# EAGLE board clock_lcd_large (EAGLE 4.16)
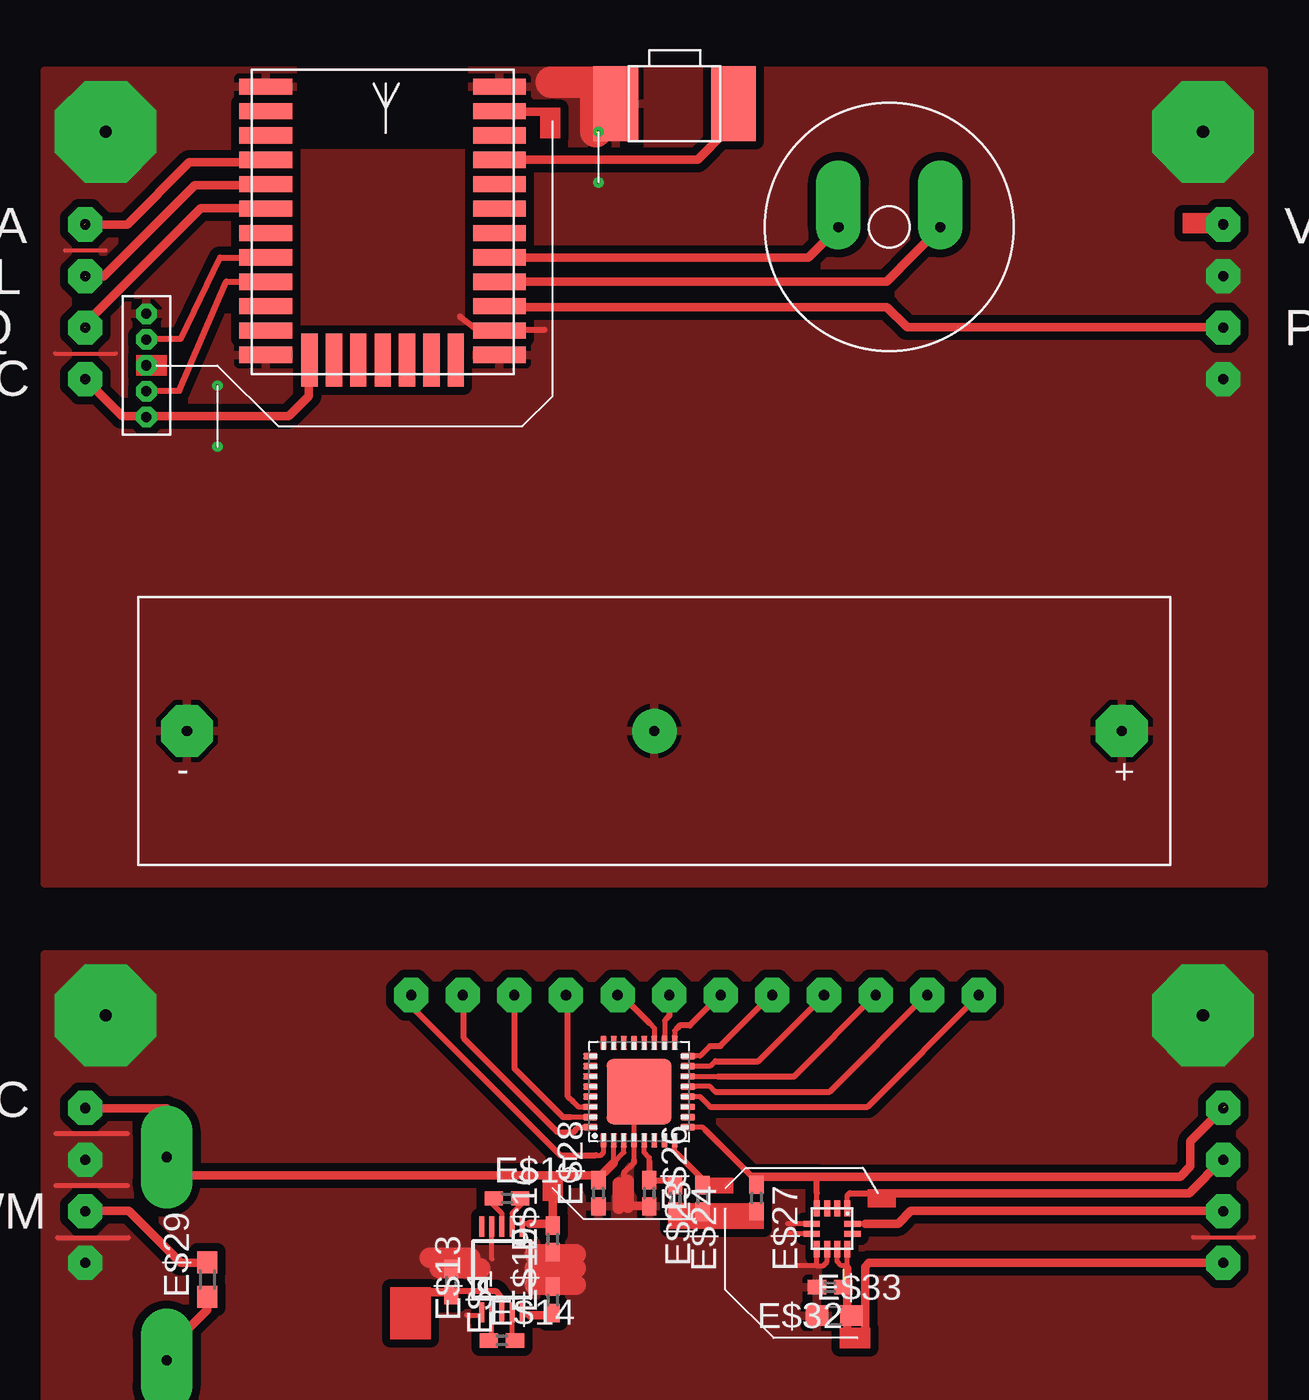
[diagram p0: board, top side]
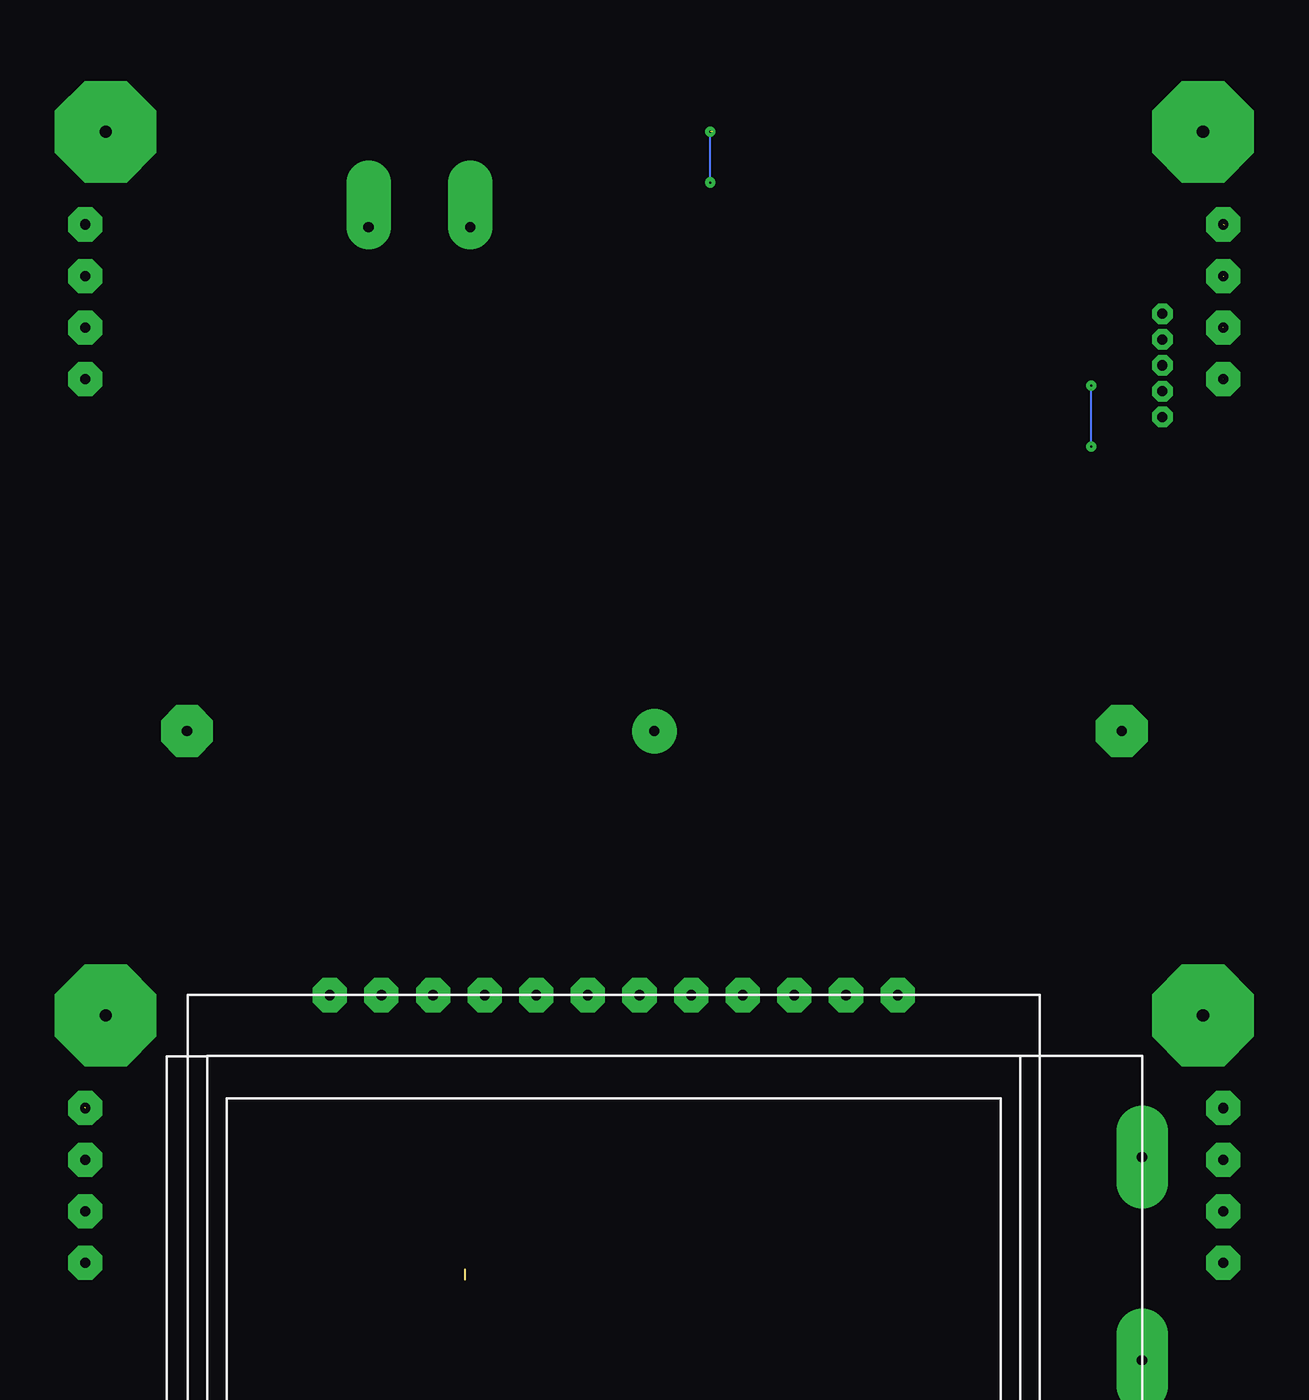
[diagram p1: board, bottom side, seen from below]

Size 0 x 0.5 mm. Coordinates in mm from the lower left corner, seen from the top.
Outline: 0,0 0,0.5
Copper layers (1*16): Top 0.035mm / dielectric 1.5mm / Bottom 0.035mm
Design rules "default": minimum track width 10mil, minimum drill 24mil, track to track 8mil, track to pad 8mil, pad to pad 8mil, via to via 8mil, smd to smd 8mil, copper to edge 40mil, drill to drill 8mil, minimum pad ring 10mil, minimum via ring 8mil, stop-mask expansion 4mil, vias tented up to drill 0mil, thermal gap 10mil

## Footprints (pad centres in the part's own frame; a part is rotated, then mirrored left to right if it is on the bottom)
C0402 = smd 0.9 x 0.7: 1 -0.65,0; 2 0.65,0
HEADER5SH = drill 0.5 octagon: P$1 -2.54,0; P$2 -1.27,0; P$3 0,0; P$4 2.54,0; P$5 1.27,0
BUZZ_12MM = drill 0.5 pad 2.184 offset: P$1 -2.5,0; P$2 2.5,0
ALI_4D_12 = drill 0.5 pad 1.676 octagon: 1 -13.97,0; 2 -11.43,0; 3 -8.89,0; 4 -6.35,0; 5 -3.81,0; 6 -1.27,0; 7 1.27,0; 8 3.81,0; 9 6.35,0; 10 8.89,0; 11 11.43,0; 12 13.97,0 | drill 0.5 pad 2.54 long: A -26,7.97; K -26,17.97
MSOP10 = smd 0.25 x 1: 1 -1,-2.113; 2 -0.5,-2.113; 3 0,-2.113; 4 0.5,-2.113; 5 1,-2.113; 6 1,2.113; 7 0.5,2.113; 8 0,2.113; 9 -0.5,2.113; 10 -1,2.113
AAA_MPD = drill 0.5 pad 2.184 round: P$1 0,0 | drill 0.5 pad 2.54 octagon: P$2 23,0; P$3 -23,0
QFN32 = smd 0.7 x 0.3: 1 -2.15,2; 2 -2.15,1.5; 3 -2.15,1; 4 -2.15,0.5; 5 -2.15,0; 6 -2.15,-0.5; 7 -2.15,-1; 8 -2.15,-1.5; 17 2.65,-1.5; 18 2.65,-1; 19 2.65,-0.5; 20 2.65,0; 21 2.65,0.5; 22 2.65,1; 23 2.65,1.5; 24 2.65,2 | smd 0.3 x 0.7: 9 -1.5,-2.15; 10 -1,-2.15; 11 -0.5,-2.15; 12 0,-2.15; 13 0.5,-2.15; 14 1,-2.15; 15 1.5,-2.15; 16 2,-2.15; 25 2,2.65; 26 1.5,2.65; 27 1,2.65; 28 0.5,2.65; 29 0,2.65; 30 -0.5,2.65; 31 -1,2.65; 32 -1.5,2.65 | smd 3.2 x 3.2: EXP 0.25,0.25
R0603 = smd 1.1 x 1: 1 -0.85,0; 2 0.85,0
LGA12 = smd 0.8 x 0.3: 1 -0.75,0.5; 2 -0.75,0; 3 -0.75,-0.5; 4 -0.75,-1; 7 1.25,-1; 8 1.25,-0.5; 9 1.25,0; 10 1.25,0.5 | smd 0.3 x 0.8: 5 0,-1.25; 6 0.5,-1.25; 11 0.5,0.75; 12 0,0.75
C0603 = smd 1.1 x 1: 1 -0.85,0; 2 0.85,0
KSS = smd 2.2 x 3.7: P$1 -2.9,0; P$2 2.9,0
BGM13P = smd 2.6 x 0.8: P$1 0.7,0.95; P$2 0.7,2.15; P$3 0.7,3.35; P$4 0.7,4.55; P$5 0.7,5.75; P$6 0.7,6.95; P$7 0.7,8.15; P$8 0.7,9.35; P$9 0.7,10.55; P$10 0.7,11.75; P$11 0.7,12.95; P$12 0.7,14.15; P$13 12.2,0.95; P$14 12.2,2.15; P$15 12.2,3.35; P$16 12.2,4.55; P$17 12.2,5.75; P$18 12.2,6.95; P$19 12.2,8.15; P$20 12.2,9.35; P$21 12.2,10.55; P$22 12.2,11.75; P$23 12.2,12.95; P$24 12.2,14.15 | smd 0.8 x 2.6: P$25 2.85,0.7; P$26 4.05,0.7; P$27 5.25,0.7; P$28 6.45,0.7; P$29 7.65,0.7; P$30 8.85,0.7; P$31 10.05,0.7

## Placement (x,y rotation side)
E$1  [C0402]  not placed on the board
E$2  [HEADER5SH]  not placed on the board
E$3  [BUZZ_12MM]  2.25,51.81 0 top  (outside the outline)
E$4  [ALI_4D_12]  -7.31,14 180 bottom
E$13  [MSOP10]  not placed on the board
E$14  [C0402]  not placed on the board
E$15  [C0402]  not placed on the board
E$16  [C0402]  not placed on the board
E$19  [C0402]  not placed on the board
E$21  [AAA_MPD]  not placed on the board
E$22  [QFN32]  not placed on the board
E$23  [C0402]  not placed on the board
E$24  [C0402]  not placed on the board
E$26  [C0402]  not placed on the board
E$27  [C0402]  not placed on the board
E$28  [C0402]  not placed on the board
E$29  [R0603]  not placed on the board
E$30  [AAA_MPD]  not placed on the board
E$31  [LGA12]  -0.31,2.75 270 top
E$32  [C0402]  -0.66,-0.38 180 top
E$33  [C0603]  -0.46,-1.77 0 top
E$38  [KSS]  not placed on the board
E$39  [BGM13P]  not placed on the board

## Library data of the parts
E$1 E$14-E$16 E$19 E$23 E$24 E$26 E$27 E$32 E$33 = ref-packages
E$2 = sb
E$3 = buzzer
E$4 = display-lcd
E$13 = analog-devices
E$21 E$30 = battery
E$22 = texas
E$28 E$29 = rcl
E$31 = st-microelectronics
E$38 = switch-misc
E$39 = silabs

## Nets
GND: E$1.1 E$16.1 E$19.2 E$23.2 E$28.1 E$30.P$1 E$30.P$2 E$30.P$3 E$32.2 E$33.1
GND3: E$2.P$4 E$21.P$1 E$21.P$2 E$21.P$3 E$38.P$2 E$39.P$1 E$39.P$12 E$39.P$13 E$39.P$24
S$5: E$3.P$2

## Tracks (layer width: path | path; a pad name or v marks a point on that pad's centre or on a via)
GND  (via drill 0.5 pad 1.68, 0.6 pad 5)
  Top 0.2: 17.19,2.08 20.19,2.08
  Top 0.254: -38.69,2.06 -35.19,2.06 | -38.75,4.62 -35.25,4.62 | -38.75,7.19 -35.25,7.19 | -18.56,-1.75 -17.81,-1.75 | -17.31,1 -17.31,2.5 | -10.31,5.88 -10.31,8 | -0.81,1.25 -0.81,0.88 -1,0.69 -1.31,0.69 | -1.31,0.69 -1.31,1.25 | -1.31,0.69 -2.26,0.69 | -1.81,2.25 -2.76,2.25 | -1.81,2.75 -2.76,2.75
  Top 0.305: -10.31,5.88 -10.31,5.75 -10.81,5.25 -10.81,4.75
  Top 0.406: -9.69,3.62 -10.69,3.62
  Top 0.61: -11.06,3.52 -11.06,4.74 | -10.61,3.57 -10.61,4.85
  Top 1.016: -20.37,1.06 -18.37,1.06 | -19.87,0.56 -17.87,0.56 | -15.19,0.56 -13.19,0.56 | -15.19,-0.25 -13.19,-0.25 | -15.19,1.25 -13.19,1.25
  other vias: -37.31,5.9 -36.31,13 17.69,13 -37.31,0.82
  pour Top (isolate 0.406): -39.31,-24 -39.31,16 20.69,16 20.69,-24
GND3  (via drill 0.1 pad 0.1, 0.5 pad 1.68, 0.6 pad 5)  (1 unrouted)
  Top 0.2: -38.81,45.58 -35.81,45.58 | -38.31,50.67 -36.31,50.67
  Top 0.305: -14.73,46.75 -17.68,46.75 -18.06,46.75 -18.88,47.41
  Top 1.55: -12.19,58.94 -14.37,58.94 | -12.19,58.94 -11.06,58.94 | -12.19,56.5 -12.19,58.94
  Bottom 0.1: v-30.81,41 v-30.81,44 | v-12.06,54 v-12.06,56.5
  other vias: -36.31,56.5 18.69,49.4 17.69,56.5 18.69,44.32
  pour Top (isolate 0.406): -39.31,19.5 -39.31,59.5 20.69,59.5 20.69,19.5
S$1
  Top 0.406: -31.31,-1 -31.31,-1.5 -32.81,-3
S$2
  Top 0.254: -8.69,12.88 -8.81,12.75 -8.81,12
  Top 0.305: -8.69,12.88 -8.56,13 -8.56,14.12
S$3
  Top 0.406: -16.19,55.12 -7.19,55.12 -5.81,56.5
S$4
  Top 0.406: -16.06,50.31 -1.75,50.31 -0.25,51.81 -0.19,51.81
S$5
  Top 0.406: -16.37,49.12 2.13,49.12 E$3.P$2
S$7  (via drill 0.5 pad 1.68)
  other vias: 18.69,0.82
S$8
  Top 0.406: -37.31,3.38 -35.19,3.38 -32.62,0.81 -31.25,0.81
S$9
  Top 0.254: -9.56,12.62 -9.31,12.38 -9.31,12
  Top 0.305: -9.56,12.62 -11.06,14.12
S$10  (via drill 0.5 pad 1.68)
  other vias: -37.31,8.44
S$11  (via drill 0.5 pad 1.68)  (1 unrouted)
  Top 0.406: -1.25,5.06 16.56,5.06 17.06,5.56 17.06,6.81 18.75,8.5
  other vias: 18.69,8.44
S$12
  Top 0.254: -17.31,-3 -17.31,-2
S$13
  Top 0.254: -16.31,-3 -16.31,-2
S$14
  Top 0.254: -16.81,-1.5 -16.81,-0.88 -17,-0.69
  Top 0.305: -17,-0.69 -17.12,-0.56 -19.19,-0.56
S$15
  Top 0.254: -15.44,2.75 -15.81,2.75
  Top 0.406: -15.44,2.75 -14.31,2.75
S$16
  Top 0.254: -15.44,-1.75 -15.81,-1.75
  Top 0.406: -15.44,-1.75 -14.31,-1.75
S$17
  Top 0.406: 1.06,-2.88 1.06,0.62 1.25,0.81 18.69,0.81
S$18  (via drill 0.5 pad 1.68)
  other vias: 18.69,51.94
S$19
  Top 0.254: -12.19,6.12 -11.94,6.12 -11.81,6.25 -11.81,6.5
  Top 0.305: -12.19,6.12 -13.94,6.12 -21.31,13.5 -21.31,14.12
S$20
  Top 0.254: -13.19,7.38 -13.06,7.5 -12.81,7.5
  Top 0.305: -13.19,7.38 -13.31,7.25 -14.06,7.25 -18.69,11.88 -18.69,14.12
S$21
  Top 0.254: -13.44,8 -12.81,8
  Top 0.305: -13.44,8 -13.81,8 -16.19,10.38 -16.19,14.12
S$22
  Top 0.305: -34.31,46.31 -32.62,46.31 -30.69,50.31 -29.37,50.31
S$23
  Top 0.305: -34.31,43.75 -32.69,43.75 -30.37,49.12 -28.75,49.12
S$24  (via drill 0.5 pad 1.68)
  other vias: -37.31,3.36
S$25  (via drill 0.5 pad 1.68)
  other vias: 18.69,46.86
S$26
  Top 0.254: -16.81,3 -16.81,3.25 -17.31,3.75
S$27
  Top 0.254: -16.31,3 -16.31,3.25 -15.81,3.75
S$28
  Top 0.406: -14.31,3 -14.31,4.5
S$29
  Top 0.406: -19.31,-0.62 -20.81,-0.62
S$41
  Top 0.254: -13.31,8.75 -13.06,8.5 -12.81,8.5
  Top 0.305: -13.31,8.75 -13.56,9 -13.56,14.12
S$48
  Top 0.254: -7.31,10 -6.19,10
  Top 0.305: -6.19,10 -2.44,10 1.56,14
S$49
  Top 0.254: -6.31,10.75 -6.56,10.5 -7.81,10.5
  Top 0.305: -0.94,14 -4.19,10.75 -6.31,10.75
S$50
  Top 0.254: -6.56,11.5 -7.06,11 -7.31,11
  Top 0.305: -6.56,11.5 -6.06,11.5 -3.56,14
S$51
  Top 0.254: -8.19,12.38 -8.31,12.25 -8.31,12
  Top 0.305: -8.19,12.38 -8.06,12.5 -7.56,12.5 -5.94,14.12
S$52
  Top 0.254: -6.31,9.25 -6.56,9.5 -7.31,9.5
  Top 0.305: 4.06,14 -0.69,9.25 -6.31,9.25
S$53
  Top 0.254: -7.81,7.5 -6.94,7.5 -6.81,7.38
  Top 0.305: -4.19,4.75 -6.81,7.38
S$54
  Top 0.254: -6.56,8.5 -7.06,9 -7.81,9
  Top 0.305: -6.56,8.5 1.19,8.5 6.69,14
S$55
  Top 0.254: -8.19,6.19 -8.31,6.31 -8.31,6.5
  Top 0.305: -6.94,4.94 -8.19,6.19
S$56
  Top 0.254: -9.81,6.5 -9.81,6.25 -9.56,6 -9.56,5.81
  Top 0.305: -9.56,5.81 -9.56,5
S$57
  Top 0.305: -9.31,4.88 -8.31,4.88
S$58
  Top 0.254: -10.81,6.5 -10.81,6.25 -11.31,5.75 -11.31,6.5
  Top 0.406: -11.81,5.25 -11.31,5.75
S$59
  Top 0.254: -1.31,3.75 -1.31,4.25
  Top 0.305: -1.31,4.25 -1.31,5.06
  Top 0.406: -1.31,5.06 -4.44,5.06
S$60
  Top 0.254: 0.19,0.69 0.19,1.25 | 0.19,0.55 0.19,0.69 | 0.19,0.69 -0.11,0.69 -0.31,0.89 -0.31,1.75
  Top 0.406: 0.19,-2.77 0.19,0.55
S$61
  Top 0.254: 1.06,2.75 0.69,2.75
  Top 0.406: 1.06,2.75 2.69,2.75 3.31,3.38 18.69,3.38
S$75  (via drill 0.5 pad 1.68)
  other vias: 18.69,5.9
S$79
  Top 0.254: 0.19,3.75 0.19,4.12
  Top 0.305: 0.19,4.12 0.31,4.25 2.63,4.25
  Top 0.406: 2.63,4.25 17,4.25 18.69,5.94
S$80  (via drill 0.5 pad 1.68)
  other vias: 18.69,3.36
S$81
  Top 0.406: -37.31,8.44 -33.31,8.44 -33.31,5.12 -12.44,5.12
S$83  (via drill 0.5 pad 1.68)  (1 unrouted)
  Top 0.406: -37.37,51.94 -35.25,51.94 -32.19,55 -29.31,55
  other vias: -37.31,51.94
S$85  (via drill 0.5 pad 1.68)  (1 unrouted)
  Top 0.406: -26.31,44.5 -26.31,43.5 -27.31,42.5 -35.5,42.5 v-37.31,44.31
S$86  (via drill 0.5 pad 1.68)  (1 unrouted)
  Top 0.406: -37.31,49.38 -36.44,49.38 -31.94,53.88 -28.44,53.88
  other vias: -37.31,49.4
S$87  (via drill 0.5 pad 1.68)  (1 unrouted)
  Top 0.406: -37.31,46.88 -37.25,47.12 -31.62,52.75 -29.06,52.75
  other vias: -37.31,46.86
S$93
  Top 0.406: -16.31,57.5 -14.31,57.5
S$94
  Top 0.406: -17.19,47.88 2.13,47.88 3.13,46.88 18.69,46.88
(copper drawn outside any net)
  shapes: Top area x9

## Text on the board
tPlace: SDA | VCC | SCL | IRQ | PWM | VCC | VCC | SDA | SCL | PWM | IRQ | VCC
